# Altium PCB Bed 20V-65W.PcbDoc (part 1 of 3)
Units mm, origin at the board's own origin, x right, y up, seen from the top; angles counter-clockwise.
Board outline 82.02 x 73.67 mm, 2 copper layers (Top Layer, Bottom Layer); 0 components, 1 nets, 2 pads, 0 vias.
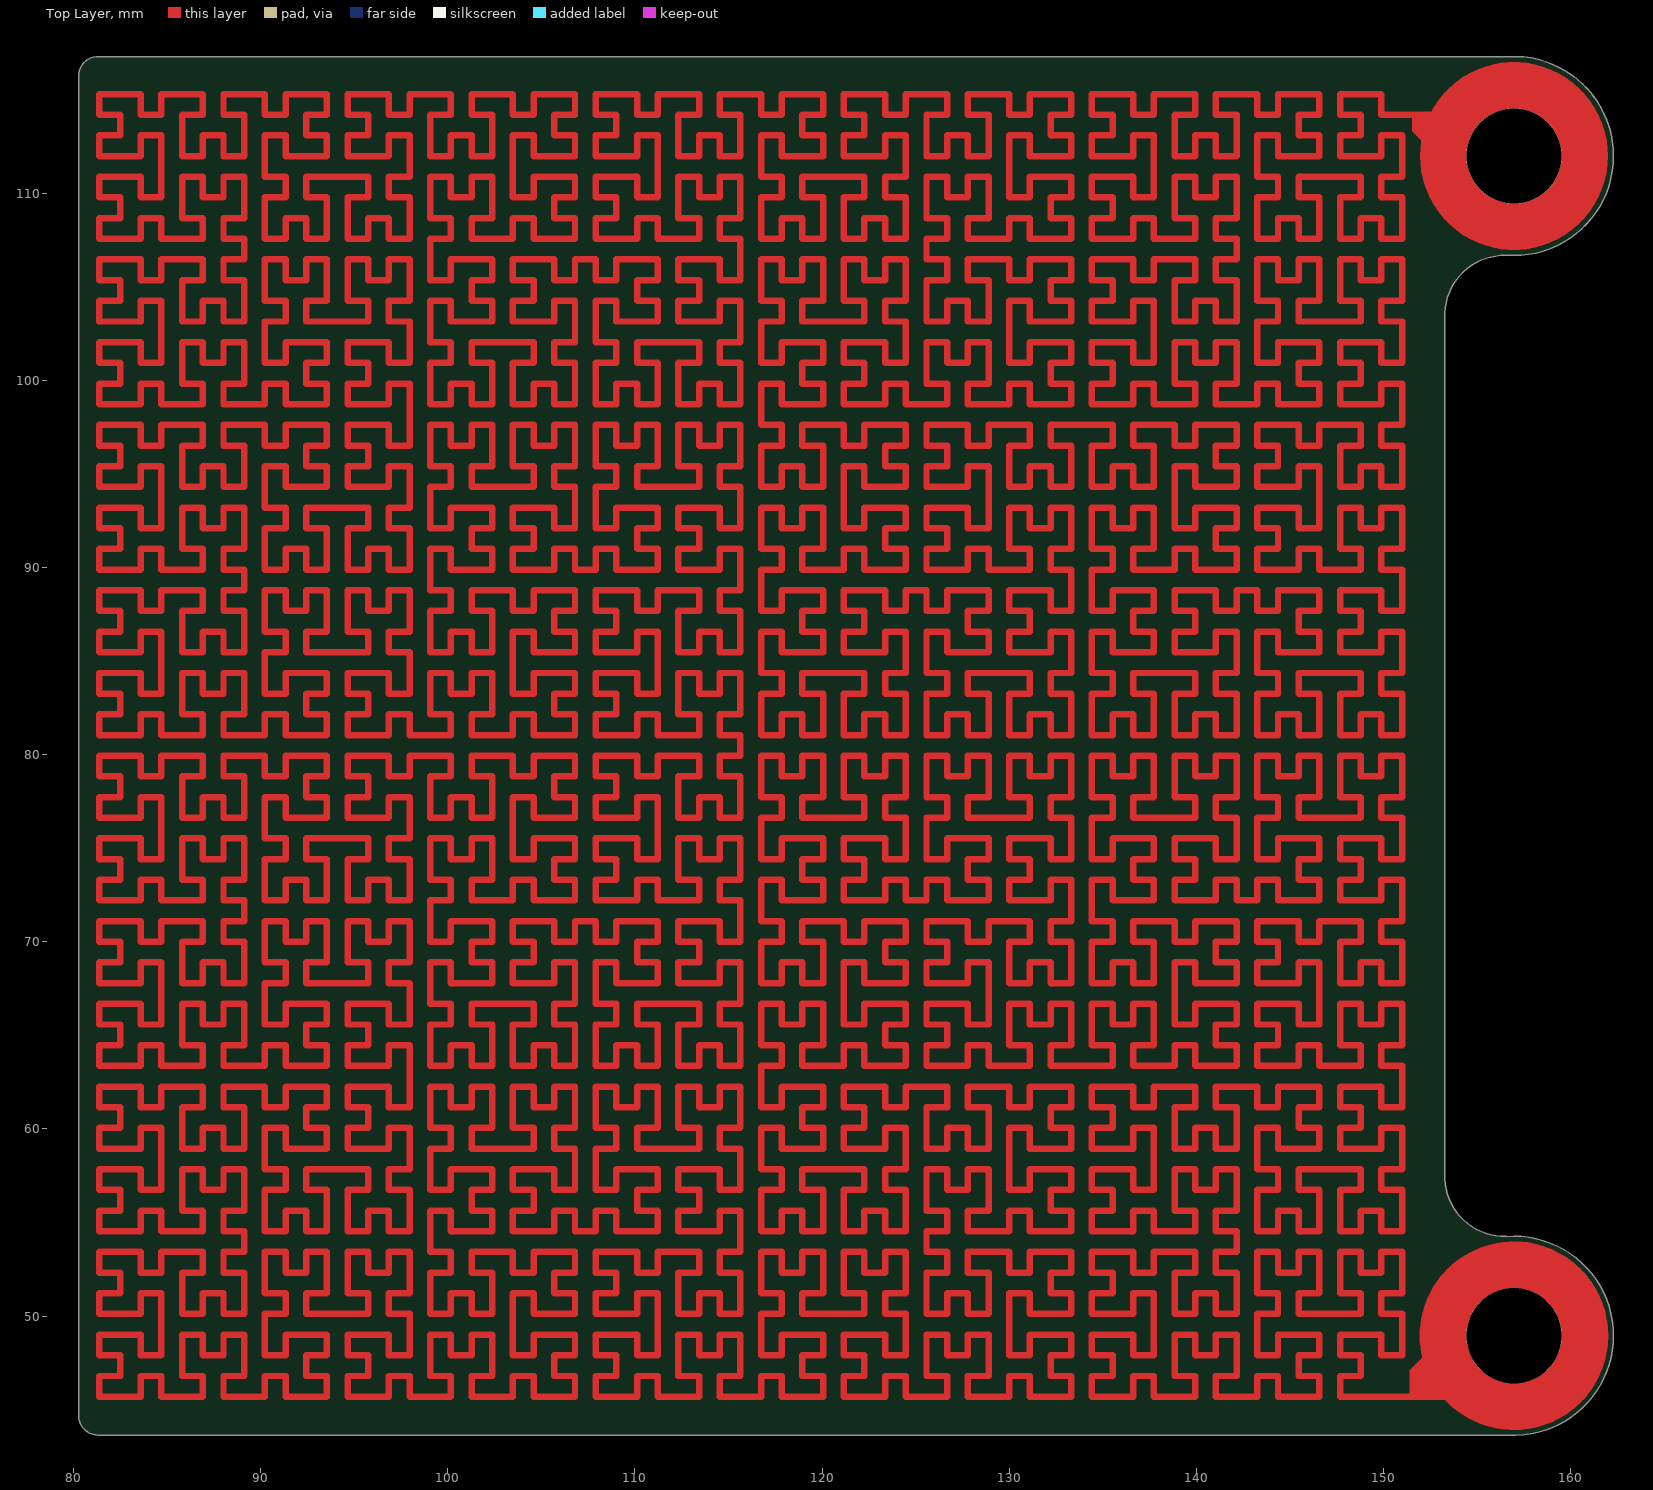
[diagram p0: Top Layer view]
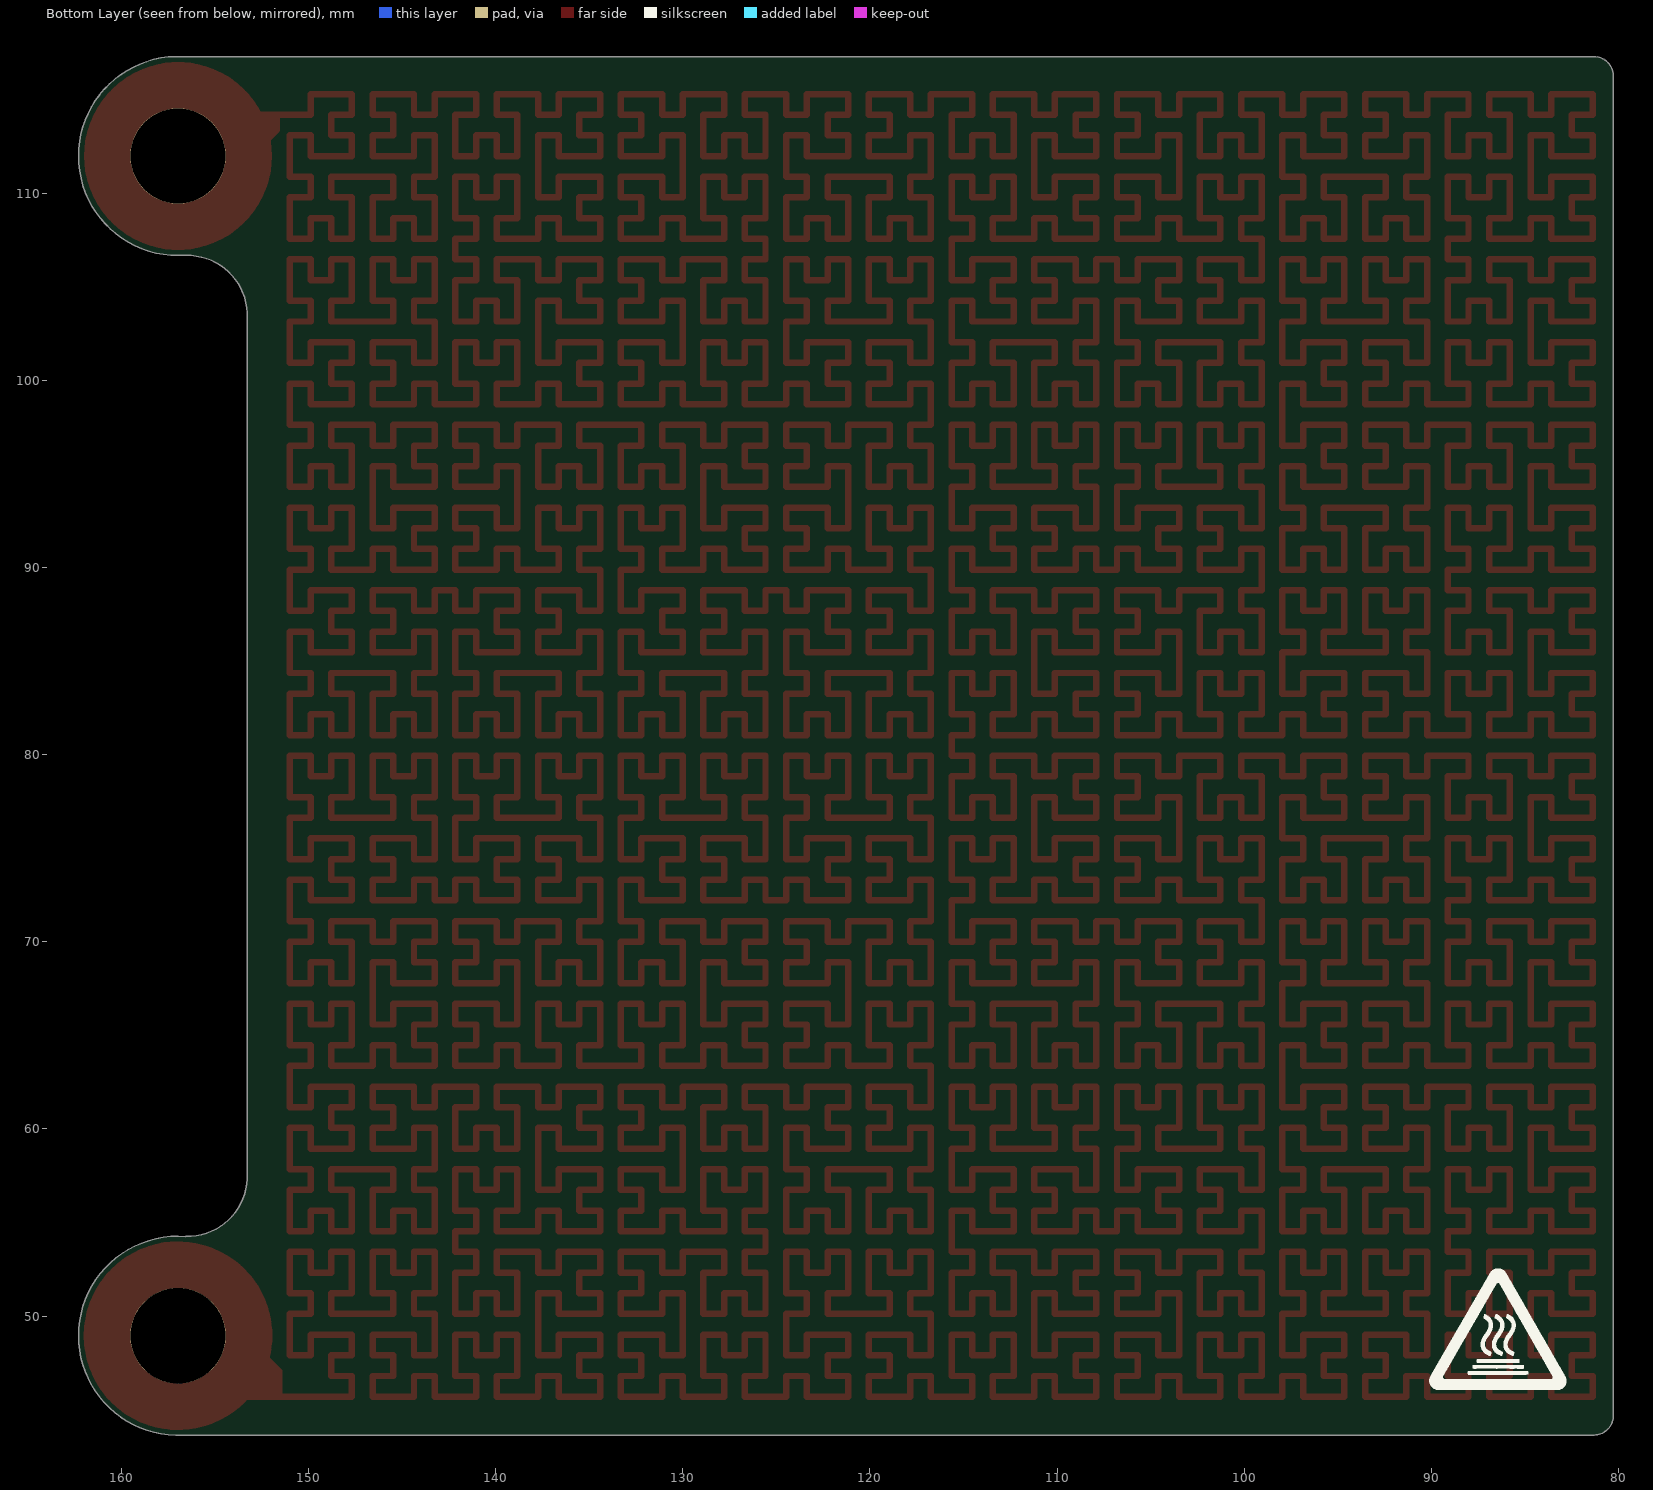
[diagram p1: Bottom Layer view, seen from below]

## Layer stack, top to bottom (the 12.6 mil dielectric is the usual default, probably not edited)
Top Solder: solder mask 0.0102, Solder Resist, Dk 3.5
Top Layer: signal copper 0.0356
Dielectric 1: dielectric 0.32, FR-4, Dk 4.8
Bottom Layer: signal copper 0.0356
Bottom Solder: solder mask 0.0102, Solder Resist, Dk 3.5

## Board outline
80.265,44.704 ccw(c81.318,44.691) 81.305,43.638 81.28,43.637 157.099,43.637 157.099,43.631 ccw(c156.972,48.947) 162.289,48.947 ccw(c156.972,48.947) 156.564,54.248 156.54,54.255 cw(c156.486,57.471) 153.272,57.329 153.272,57.355 153.272,103.606 cw(c156.485,103.464) 156.54,106.68 156.564,106.687 ccw(c156.972,111.989) 162.289,111.989 ccw(c156.972,111.989) 157.099,117.304 157.099,117.298 81.28,117.298 81.305,117.297 ccw(c81.318,116.244) 80.265,116.231

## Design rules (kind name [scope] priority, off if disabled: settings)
Clearance [All] p1: gap=0 ignorepadtopadclearanceinfootprint=FALSE
HoleSize [All] p1: absolutevalues=TRUE maxlimit=6 minlimit=0.025 maxpercent=80.000 minpercent=20.000
NetAntennae [InNet('No Net')] p1: netantennaetolerance=0
PolygonConnect [All] p1: connectstyle=Relief reliefconductorwidth=0.254 reliefentries=4 polygonreliefangle="90 Angle" airgapwidth=0.254
RoutingVias [All] p1: holewidth=0.711 width=1.27 viastyle="Through Hole" minholewidth=0.711 minwidth=1.27 maxholewidth=0.711 maxwidth=1.27
ShortCircuit [All] p1: allowed=TRUE
SolderMaskExpansion [All] p1: expansion=0.102 istentingtop=FALSE
Width [All] p1: maxlimit=3 minlimit=0.254 preferedwidth=0.254
27 further rules are at their usual default settings.

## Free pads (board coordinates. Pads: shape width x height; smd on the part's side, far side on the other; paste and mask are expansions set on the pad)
  round 5.1 hole 5.1: 8(156.972,111.989) 8(156.972,48.947)

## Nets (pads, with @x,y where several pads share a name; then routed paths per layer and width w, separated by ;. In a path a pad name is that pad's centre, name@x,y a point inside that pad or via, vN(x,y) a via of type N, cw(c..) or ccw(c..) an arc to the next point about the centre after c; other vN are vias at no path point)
Bed20V: pad.8 | length 4604.2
